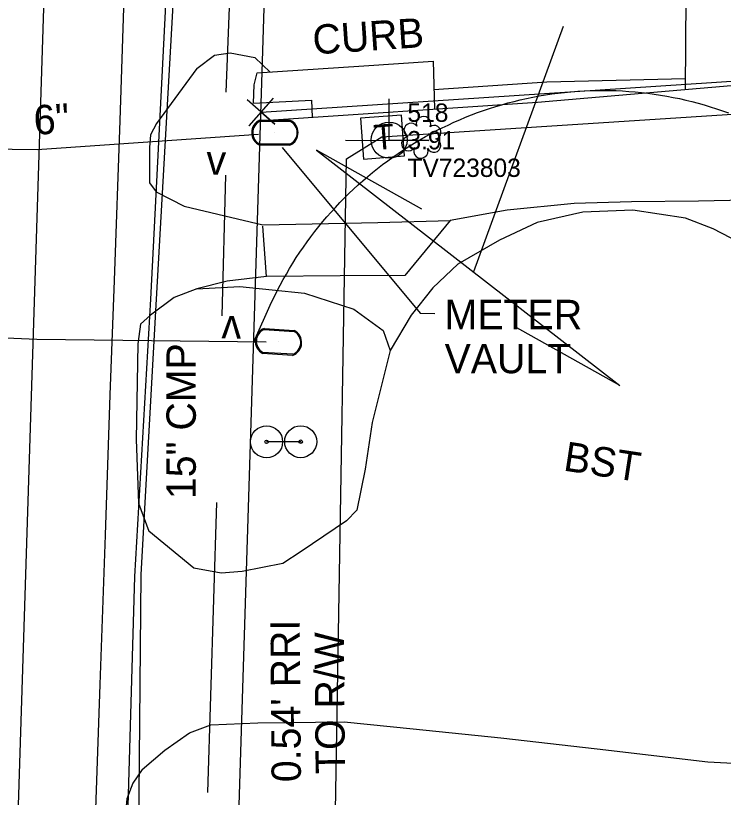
# Model space of a CAD drawing. Extents: x 3040896 to 3051146, y 687568 to 732976.
# Drawn here: x 3049827.2 to 3049923.5, y 689589.9 to 689696.4 of the extents above; entities that cross this region are included whole.
import ezdxf

# ---------------------------------------------------------------- set-up
doc = ezdxf.new("R2010")
doc.units = 0
for name, color, linetype in [('Exist Horizontal Alignment', 7, 'Continuous'), ('Exist Other Culture Area Outline', 7, 'Continuous'), ('Exist Other Culture Billboard Cableway', 7, 'Continuous'), ('Exist Other Culture Fence Line', 7, 'Continuous'), ('Exist Other Culture Located Object CELL', 7, 'Continuous'), ('Exist Property Corner CELL', 7, 'Continuous'), ('Exist Property Line', 7, 'Continuous'), ('Exist Property Line Text', 7, 'Continuous'), ('Exist Property Same Owner Line CELL', 7, 'Continuous'), ('Exist Right of Way Line', 7, 'Continuous'), ('Exist Roads Change in Surface', 7, 'Continuous'), ('Exist Roads Curbs', 7, 'Continuous'), ('Exist Roads Curbs Text', 7, 'Continuous'), ('Exist Roads EOP', 7, 'Continuous'), ('Exist Roads EOP Other', 7, 'Continuous'), ('Exist Roads EOP Other Text', 7, 'Continuous'), ('Exist Roads EOT', 7, 'Continuous'), ('Exist Roads Soil', 7, 'Continuous'), ('Exist Structure Minor Culvert Topo', 7, 'Continuous'), ('Exist Structure Minor Culvert Topo Terminator', 7, 'Continuous'), ('Exist Structure Minor Pipes CMP 15 Inch', 7, 'Continuous'), ('Exist Structure Minor Pipes CMP 15 Inch Text', 7, 'Continuous'), ('Exist Structure Minor Pipes CMP 18 Inch', 7, 'Continuous'), ('Exist Utilities Power Joint Use Telephone CELL', 7, 'Continuous'), ('Exist Utilities Power Joint Use Telephone Cogo Comment', 7, 'Continuous'), ('Exist Utilities Power Joint Use Telephone Cogo Elevation', 7, 'Continuous'), ('Exist Utilities Power Joint Use Telephone Cogo Number', 7, 'Continuous'), ('Exist Utilities Telephone Pedestal CELL', 7, 'Continuous'), ('Exist Utilities Telephone UG Cable', 7, 'Continuous'), ('Exist Utilities Telephone UG Conduit SUE', 7, 'Continuous'), ('Exist Utilities Water Meter CELL', 7, 'Continuous'), ('Exist Utilities Water Meter Leader', 7, 'Continuous'), ('Exist Utilities Water Meter Text', 7, 'Continuous'), ('Exist Utilities Water UG Line SUE', 7, 'Continuous'), ('Exist Utilities Water UG Line SUE Text', 7, 'Continuous'), ('Exist Vegetation Shrub CELL', 7, 'Continuous')]:
    doc.layers.add(name, color=color, linetype=linetype)

# ---------------------------------------------------------------- blocks, each defined once
blk = doc.blocks.new('EXIST UTILITIES POWER JOINT USE TELEPHONE')
at = {"layer": 'Exist Utilities Power Joint Use Telephone CELL'}
blk.add_line((0, 0), (0, 0), dxfattribs=at)
blk.add_lwpolyline([(-0.1188, 0), (0.108, -0.0008), (0, -0.0004), (0, 0.1125)], dxfattribs=at)
blk.add_circle((0, 0.0001), 0.049, dxfattribs=at)

msp = doc.modelspace()

# ---------------------------------------------------------------- linework, layer by layer
at = {"layer": 'Exist Horizontal Alignment'}
msp.add_line((3049785.41, 688254.93), (3049834.01, 689792.8), dxfattribs=at)
at = {"layer": 'Exist Other Culture Area Outline'}
msp.add_lwpolyline([(3049859.52, 689684.47), (3049867.43, 689684.84), (3049867.52, 689682.53)], dxfattribs=at)
at = {"layer": 'Exist Other Culture Billboard Cableway'}
msp.add_lwpolyline([(3049865.96, 689638.36), (3049861.32, 689638.35)], dxfattribs=at)
at = {"layer": 'Exist Other Culture Fence Line'}
msp.add_lwpolyline([(3049860.24, 689682.04), (3049898.19, 689684.61), (3049928.73, 689687.22), (3049975.98, 689689.93), (3050002.9, 689691.81), (3050039.15, 689694.31), (3050052.67, 689694.85)], dxfattribs=at)
at = {"layer": 'Exist Other Culture Located Object CELL'}
for centre, radius in [((3049861.32, 689638.35), 2.18), ((3049865.96, 689638.36), 2.18), ((3049861.32, 689638.35), 0.24), ((3049865.96, 689638.36), 0.24)]:
    msp.add_circle(centre, radius, dxfattribs=at)
at = {"layer": 'Exist Property Corner CELL'}
msp.add_line((3049860.56, 689683.25), (3049860.56, 689683.25), dxfattribs=at)
msp.add_lwpolyline([(3049862.21, 689685.13), (3049858.92, 689681.37), (3049860.56, 689683.25), (3049862.44, 689681.6), (3049858.68, 689684.9)], dxfattribs=at)
at = {"layer": 'Exist Property Line'}
msp.add_line((3049860.56, 689683.25), (3050168.59, 689703.53), dxfattribs=at)
at = {"layer": 'Exist Property Same Owner Line CELL'}
for points in [[(3049901.66, 689694.91), (3049889.46, 689661.48)], [(3049882.43, 689670.01), (3049868.1, 689678.04), (3049909.38, 689646.03), (3049895.05, 689654.06)]]:
    msp.add_lwpolyline(points, dxfattribs=at)
at = {"layer": 'Exist Right of Way Line'}
msp.add_line((3049846.34, 689233.08), (3049865.5, 689839.45), dxfattribs=at)
msp.add_lwpolyline([(3049859.57, 689651.94), (3049862.01, 689657.34), (3049862.39, 689658.12), (3049862.77, 689658.9), (3049863.17, 689659.67), (3049863.58, 689660.44), (3049864.01, 689661.19), (3049864.45, 689661.94), (3049864.9, 689662.69), (3049865.36, 689663.42), (3049865.84, 689664.15), (3049866.33, 689664.86), (3049866.83, 689665.57), (3049867.35, 689666.27), (3049867.87, 689666.96), (3049868.41, 689667.64), (3049868.96, 689668.32), (3049869.52, 689668.98), (3049870.1, 689669.63), (3049870.68, 689670.27), (3049871.28, 689670.91), (3049871.89, 689671.53), (3049872.5, 689672.14), (3049873.13, 689672.74), (3049873.77, 689673.33), (3049874.42, 689673.9), (3049875.08, 689674.47), (3049875.75, 689675.02), (3049876.42, 689675.57), (3049877.11, 689676.1), (3049877.81, 689676.62), (3049878.51, 689677.12), (3049879.23, 689677.62), (3049879.95, 689678.1), (3049880.68, 689678.57), (3049881.42, 689679.02), (3049882.17, 689679.47), (3049882.92, 689679.9), (3049883.69, 689680.31), (3049884.45, 689680.72), (3049885.23, 689681.11), (3049886.01, 689681.48), (3049886.8, 689681.85), (3049887.6, 689682.2), (3049888.4, 689682.53), (3049889.21, 689682.85), (3049890.02, 689683.16), (3049890.84, 689683.45), (3049891.66, 689683.73), (3049892.49, 689683.99), (3049893.32, 689684.24), (3049894.16, 689684.48), (3049895, 689684.7), (3049895.84, 689684.9), (3049896.69, 689685.09), (3049897.54, 689685.27), (3049898.39, 689685.43), (3049899.25, 689685.58), (3049900.11, 689685.71), (3049900.97, 689685.82), (3049901.83, 689685.92), (3049902.7, 689686.01), (3049903.68, 689686.09), (3049904.54, 689686.14), (3049905.41, 689686.17), (3049906.28, 689686.19), (3049907.15, 689686.2), (3049908.02, 689686.18), (3049908.88, 689686.16), (3049909.75, 689686.12), (3049910.62, 689686.06), (3049911.48, 689685.99), (3049912.35, 689685.9), (3049913.21, 689685.8), (3049914.07, 689685.68), (3049914.93, 689685.55), (3049915.79, 689685.4), (3049916.64, 689685.24), (3049917.49, 689685.07), (3049918.34, 689684.87), (3049919.18, 689684.67), (3049920.02, 689684.45), (3049920.86, 689684.21), (3049921.69, 689683.96), (3049922.52, 689683.7), (3049923.34, 689683.42), (3049924.16, 689683.12)], dxfattribs=at)
at = {"layer": 'Exist Roads Change in Surface'}
msp.add_lwpolyline([(3049861.31, 689660.84), (3049860.8, 689667.72)], dxfattribs=at)
at = {"layer": 'Exist Roads Curbs'}
for points in [[(3049918.31, 689686.33), (3049918.41, 689698.86), (3049918.62, 689714.92), (3049919, 689730.83), (3049919.46, 689755.99), (3049919.67, 689766.33)], [(3049859.62, 689686.94), (3049860.04, 689688.57), (3049874.57, 689689.54), (3049883.97, 689690.17), (3049884.16, 689683.66)], [(3049859.52, 689684.47), (3049859.62, 689686.94)]]:
    msp.add_lwpolyline(points, dxfattribs=at)
at = {"layer": 'Exist Roads EOP'}
msp.add_lwpolyline([(3049845.52, 689655.6), (3049844.17, 689654.36), (3049843.78, 689651.7), (3049843.56, 689638.64), (3049843.91, 689629.97), (3049845.28, 689626.2)], dxfattribs=at)
at = {"layer": 'Exist Roads EOP Other'}
for points in [[(3049851.85, 689689.15), (3049854.24, 689690.97), (3049856.37, 689691.3), (3049859.72, 689690.65), (3049861.82, 689688.69)], [(3049851.85, 689689.15), (3049846.32, 689681.67), (3049845.54, 689680.12), (3049845.37, 689678.4), (3049845.38, 689673.61), (3049846.28, 689672.39)], [(3049884.08, 689686.32), (3049899.44, 689687.38), (3049918.32, 689687.82)], [(3049846.28, 689672.39), (3049850.12, 689670.41), (3049855.65, 689669.11), (3049860.79, 689667.91), (3049876.46, 689668.19), (3049886.29, 689668.47), (3049880.14, 689660.97), (3049871.34, 689660.94), (3049861.31, 689660.84), (3049855.95, 689660.21), (3049851.85, 689659.17), (3049848.75, 689657.98), (3049845.52, 689655.6)], [(3049926.88, 689664.85), (3049922.08, 689667.36), (3049918.32, 689668.79), (3049911.13, 689669.88), (3049904.35, 689669.61), (3049898.12, 689668.2), (3049893.01, 689665.81), (3049887.32, 689662.53), (3049883.95, 689659.33), (3049881, 689655.61), (3049878.15, 689650.77), (3049875.7, 689640.99), (3049874.71, 689634.63), (3049873.62, 689629.05), (3049872.18, 689627.6), (3049866.03, 689623.39), (3049863.53, 689621.8), (3049857.99, 689620.69), (3049855.13, 689620.46), (3049851.4, 689621.15), (3049845.28, 689626.2)], [(3049844.38, 689593.74), (3049847.46, 689596.37), (3049850.82, 689598.72), (3049853.72, 689599.8), (3049860.14, 689600.09), (3049871.89, 689600.2), (3049881.28, 689599.26), (3049893.2, 689598.04), (3049906.31, 689596.56), (3049921.34, 689594.77), (3049937.75, 689593.9), (3049960.08, 689592.57), (3049975.41, 689591.89), (3049988.45, 689592.69), (3050000.63, 689593.73), (3050020.69, 689595.94), (3050032.67, 689596.41), (3050048.91, 689596.65), (3050062.48, 689597.47), (3050079.47, 689598.22), (3050097.85, 689599.24)], [(3049844.38, 689593.74), (3049843.14, 689591.88), (3049842.29, 689589.76), (3049842.06, 689587.22), (3049842.83, 689584.55), (3049843.77, 689583.11)]]:
    msp.add_lwpolyline(points, dxfattribs=at)
at = {"layer": 'Exist Roads EOT'}
msp.add_lwpolyline([(3049844.24, 689762.9), (3049843.56, 689743.51), (3049842.88, 689725.58), (3049842.05, 689703.05), (3049841.35, 689682.11), (3049840.58, 689660.32), (3049839.98, 689644.75), (3049839.35, 689625.65), (3049838.62, 689605.29), (3049837.88, 689583.1), (3049837.3, 689560.36), (3049836.42, 689530.18), (3049835.49, 689497.82), (3049834.77, 689472.49), (3049834.26, 689454.77), (3049833.56, 689433.52), (3049832.26, 689394.19), (3049831.41, 689367.12), (3049830.62, 689344.03), (3049829.93, 689320.91), (3049829.26, 689301.29), (3049828.74, 689281.75), (3049828.1, 689260.79), (3049827.77, 689251.31)], dxfattribs=at)
at = {"layer": 'Exist Roads Soil'}
for points in [[(3049910.95, 689671.02), (3049903.18, 689670.8), (3049894.06, 689669.9), (3049886.29, 689668.47)], [(3049932.85, 689671.36), (3049920.09, 689671.12), (3049910.95, 689671.02)], [(3049851.85, 689659.17), (3049857.7, 689659.51), (3049866.5, 689658.57), (3049873.21, 689656.4), (3049877.2, 689653.5), (3049878.15, 689650.77)]]:
    msp.add_lwpolyline(points, dxfattribs=at)
at = {"layer": 'Exist Structure Minor Culvert Topo'}
msp.add_lwpolyline([(3049855.71, 689674.67), (3049855.25, 689655.51)], dxfattribs=at)
at = {"layer": 'Exist Structure Minor Pipes CMP 15 Inch'}
msp.add_lwpolyline([(3049854.5, 689630.09), (3049853.28, 689590.62)], dxfattribs=at)
at = {"layer": 'Exist Structure Minor Pipes CMP 18 Inch'}
msp.add_lwpolyline([(3049855.8, 689685.94), (3049857.88, 689737.91)], dxfattribs=at)
at = {"layer": 'Exist Utilities Telephone Pedestal CELL'}
msp.add_line((3049877.02, 689679.86), (3049877.02, 689679.86), dxfattribs=at)
msp.add_lwpolyline([(3049874.52, 689676.84), (3049880.09, 689677.26), (3049879.67, 689682.84), (3049874.09, 689682.42), (3049874.52, 689676.84)], dxfattribs=at)
at = {"layer": 'Exist Utilities Telephone UG Cable'}
msp.add_lwpolyline([(3049859.94, 689114.99), (3049862.82, 689119.96), (3049872.17, 689676.87), (3049877.02, 689679.86), (3049980.82, 689686.59), (3050081.54, 689693.04)], dxfattribs=at)
at = {"layer": 'Exist Utilities Telephone UG Conduit SUE'}
for points in [[(3049814.97, 688681.54), (3049815.19, 688713.75), (3049817.29, 688785.86), (3049819.31, 688838.58), (3049821.31, 688904.07), (3049822.78, 688948.25), (3049824.67, 689008.14), (3049827.2, 689070.53), (3049829.22, 689113.93), (3049831.94, 689205.52), (3049833.9, 689276.46), (3049835.16, 689324.18), (3049835.85, 689361.7), (3049841.16, 689398.19), (3049840.45, 689446.03), (3049839.83, 689496.46), (3049843.38, 689620.01), (3049845.59, 689657.76), (3049849.97, 689744.2), (3049850.46, 689783.89), (3049852.96, 689821.43), (3049854.18, 689865.57), (3049858.43, 689927.4)], [(3049819.01, 688681.38), (3049818.87, 688714.58), (3049821.45, 688786.38), (3049822.69, 688838.08), (3049824.19, 688903.73), (3049825.2, 688948.29), (3049828.44, 689007.63), (3049829.82, 689071.04), (3049831.65, 689114.37), (3049834.21, 689205.23), (3049835.03, 689276.62), (3049835.93, 689324.28), (3049836.62, 689361.29), (3049843.33, 689398.29), (3049841.93, 689445.98), (3049840.71, 689496.07), (3049843.82, 689570.21), (3049844.27, 689620.28), (3049846.35, 689657.78), (3049851.2, 689743.54), (3049851.21, 689783.5), (3049853.59, 689821.65), (3049856.29, 689865.88), (3049860.69, 689927.09)]]:
    msp.add_lwpolyline(points, dxfattribs=at)
at = {"layer": 'Exist Utilities Water Meter CELL'}
for p, q in [((3049862.46, 689680.44), (3049862.46, 689680.44)), ((3049862.94, 689651.95), (3049862.94, 689651.95))]:
    msp.add_line(p, q, dxfattribs=at)
for points in [[(3049860.42, 689682.14), (3049864.49, 689682.14)], [(3049860.42, 689682), (3049864.49, 689682)], [(3049864.49, 689678.87), (3049860.39, 689678.87)], [(3049864.49, 689678.74), (3049860.39, 689678.74)], [(3049861.01, 689653.64), (3049865.08, 689653.37)], [(3049861.02, 689653.78), (3049865.09, 689653.51)], [(3049864.87, 689650.26), (3049860.78, 689650.52)], [(3049864.86, 689650.12), (3049860.77, 689650.39)]]:
    msp.add_lwpolyline(points, dxfattribs=at)
for centre, radius, start, end in [((3049861.15, 689680.43), 1.86, 113.178, 245.9794), ((3049861.16, 689680.43), 1.73, 115.3009, 243.7824), ((3049863.75, 689680.44), 1.86, 293.6483, 66.3084), ((3049863.76, 689680.44), 1.73, 295.1272, 64.8728), ((3049861.64, 689652.03), 1.86, 109.4263, 242.2277), ((3049861.65, 689652.03), 1.73, 111.5492, 240.0306), ((3049864.23, 689651.86), 1.86, 289.8966, 62.5566), ((3049864.24, 689651.86), 1.73, 291.3754, 61.1211)]:
    msp.add_arc(centre, radius, start, end, dxfattribs=at)
at = {"layer": 'Exist Utilities Water Meter Leader'}
msp.add_lwpolyline([(3049863.44, 689678.4), (3049882.23, 689655.87), (3049884.22, 689655.81)], dxfattribs=at)
at = {"layer": 'Exist Utilities Water UG Line SUE'}
for points in [[(3049806.17, 689678.44), (3049830.11, 689678.14), (3049860.23, 689680.24)], [(3049805.12, 689657), (3049805.12, 689653.4), (3049830.08, 689652.34), (3049861.24, 689651.98)]]:
    msp.add_lwpolyline(points, dxfattribs=at)
at = {"layer": 'Exist Vegetation Shrub CELL'}
msp.add_line((3049882.44, 689679.62), (3049882.44, 689679.62), dxfattribs=at)
for centre, radius, start, end in [((3049882.67, 689681.66), 0.99, 334.8391, 200.4717), ((3049880.96, 689680.75), 0.968, 35.8908, 245.4216), ((3049884.12, 689680.49), 0.929, 284.4567, 126.0861), ((3049880.64, 689678.92), 0.955, 95.1099, 327.9534), ((3049884.08, 689678.7), 0.937, 204.9913, 73.4601), ((3049882.31, 689677.94), 0.984, 151.2797, 21.387)]:
    msp.add_arc(centre, radius, start, end, dxfattribs=at)

# ---------------------------------------------------------------- block references
at = {"layer": 'Exist Utilities Power Joint Use Telephone CELL', "xscale": 50, "yscale": 50}
msp.add_blockref('EXIST UTILITIES POWER JOINT USE TELEPHONE', (3049877.98, 689679.41), dxfattribs=at)

# ---------------------------------------------------------------- texts
at = {"layer": 'Exist Property Line Text'}
for s, p in [("0.54' RRI", (3049866, 689592.02)), ('TO R/W', (3049871.99, 689593.14))]:
    msp.add_text(s, height=4, rotation=90.4525, dxfattribs=at).set_placement(p)
at = {"layer": 'Exist Roads Curbs Text'}
msp.add_text('CURB', height=4, rotation=3.8601, dxfattribs=at).set_placement((3049867.71, 689691.08))
at = {"layer": 'Exist Roads EOP Other Text'}
msp.add_text('BST', height=4, rotation=351.3341, dxfattribs=at).set_placement((3049901.58, 689634.45))
at = {"layer": 'Exist Structure Minor Culvert Topo Terminator'}
for rotation, p in [(358.3836, (3049853.07, 689674.74)), (178.8653, (3049857.9, 689655.45))]:
    msp.add_text('v', height=4, rotation=rotation, dxfattribs=at).set_placement(p)
at = {"layer": 'Exist Structure Minor Pipes CMP 15 Inch Text'}
msp.add_text('15" CMP', height=4, rotation=90, dxfattribs=at).set_placement((3049851.69, 689630.54))
at = {"layer": 'Exist Utilities Power Joint Use Telephone Cogo Comment'}
msp.add_text('TV723803', height=2.5, dxfattribs=at).set_placement((3049880.48, 689674.41))
at = {"layer": 'Exist Utilities Power Joint Use Telephone Cogo Elevation'}
msp.add_text('3.91', height=2.5, dxfattribs=at).set_placement((3049880.48, 689678.16))
at = {"layer": 'Exist Utilities Power Joint Use Telephone Cogo Number'}
msp.add_text('518', height=2.5, dxfattribs=at).set_placement((3049880.48, 689681.91))
at = {"layer": 'Exist Utilities Telephone Pedestal CELL'}
msp.add_text('T', height=3.42, rotation=4.3251, dxfattribs=at).set_placement((3049876.02, 689678.07))
at = {"layer": 'Exist Utilities Water Meter Text'}
for s, p in [('METER', (3049885.54, 689653.68)), ('VAULT', (3049885.54, 689647.68))]:
    msp.add_text(s, height=4, dxfattribs=at).set_placement(p)
at = {"layer": 'Exist Utilities Water UG Line SUE Text'}
msp.add_text('6"', height=4, rotation=4.0052, dxfattribs=at).set_placement((3049829.76, 689680.12))

doc.saveas('drawing.dxf')
